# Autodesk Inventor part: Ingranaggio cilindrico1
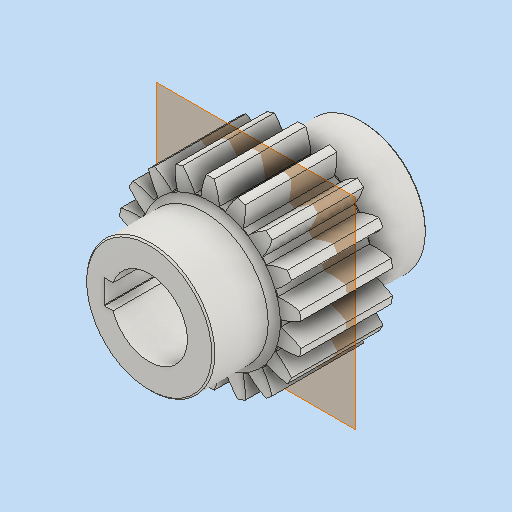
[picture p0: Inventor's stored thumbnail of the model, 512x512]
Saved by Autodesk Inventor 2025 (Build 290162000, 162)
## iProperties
CustomPartVersion: 1
Created: 2026-05
Part Number: Ingranaggio cilindrico1
Material: Acciaio inossidabile
Document SubType Name: Modeling
Designer: R5800u
Categories: <?xml version="1.0" encoding="UTF-16"?> <MemberInstance><Categories><FamilyTemplate><FamilyTemplateParameter ValueType="xs:double" Id="1" ObjectReferenceKey="da
Density: 8 g/cm^3
Appearance: Acciaio
Author: R5800u
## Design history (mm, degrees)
sketch "Sketch1"
  geometry: C1 r 30 at (0, 0)
  constraints: 1 centre point
  dimensions: "d0" = 60 diameter of C1 (= da_da)
extrude "Extrusion1" new body sketch "Sketch1" distance "d1" = 30 (= da_b); taper "d2" = 0 deg
workplane "Work Plane2"
feature "Diametro primitivo" dims "d4" = 10, "d5" = 0
workplane "Work Plane8"
workplane "Work Plane9"
feature "Ingranaggio cilindrico" dims "da_b" = 30, "da_d" = 54, "da_aw" = 162, "da_da" = 60, "da_df" = 46.5, "da_dw" = 54, angle "da_beta" = 0 deg, "da_lefttooth" = 0, "da_righttooth" = 0
sketch "Schizzo3"
  geometry: A1 r 23.25 centre (0, 0) between (-18.445, -14.154) and (-17.142, -15.707) reference; 2 further points
  constraints: 1 coincident
hole "Foro1" sketch "Schizzo3" at (0, 0) diameter "d49" = 25; stored, may be unused: countersink angle "d53" = 90 deg, drill point angle "d55" = 118 deg; dims "d50" = 6, "d51" = 4, "d52" = 2, "d54" = 8
sketch "Schizzo4"
  geometry: C1 r 12.5 at (0, 0) reference; C2 r 21 at (0, 0); 1 further point
  constraints: 1 centre point, 1 coincident
  dimensions: "d56" = 42 diameter of C2
extrude "Estrusione2" join sketch "Schizzo4" distance "d57" = 20; taper "d58" = 0 deg
node "Piano di lavoro11"
fillet "Raccordo2" dims "d60" = 2
mirror "Speculare1"
chamfer "Smusso1" distance "d61" = 0.5; stored, may be unused: second distance "d62" = 2, angle "d63" = 45 deg
node "Scanalatura2"
body "Solid1"
sketch "Sketch2"
  geometry: C1 r 30 at (0, 0) reference; C2 r 27 at (0, 0)
  constraints: 1 centre point, 1 coincident
  dimensions: "d3" = 54 diameter of C2 (= da_d)
body "Srf1"
feature "Sede chiavetta mozzo"
other parameters: "d16" = 162 (= da_aw), "d17" = 0, "d34" = 10 deg (computed from da_z), "d39" = 0, "d41" = 0, "d43" = 162 (= da_aw), "d46" = 162 (= da_aw), "d47" = 0, "d48" = 0
